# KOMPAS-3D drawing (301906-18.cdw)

Views: Вид А
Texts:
  Полумуфта
  Петров С.А.
  СПБГТИ(ТУ)
  Текст на чертеже
  Размерные надписи
  Шероховатость
  Линия-выноска #1
  Линия-выноска #2
  Линия-выноска #3
  Отклонения формы и база
  Заголовок таблицы
  Ячейка таблицы
  Стрелка вида
  Обозначение изменения
  Фигурная скобка
  Номер узла
  Марка координационной оси
  VRCB
  Выносная надпись
  Обозначение узла
  Марка/позиционное обозначение с линией-выноской
  Марка/позиционное обозначение на линии
  Марка/позиционное обозначение без линии-выноски
  Ra 2,5
  Rz 15
  1. Неуказанные предельные отклонения размеров валов h14,
  отверстий H14, остальных   IT 14/2
  Основной вид
  Rz 30
  Баранов Д.А.
  группа 364
  Сталь 12Х18Н10Т  Круг
Dimensions and other numbers on the sheet: 105.16.05.00.000; 7; 180; 220; 105; 120; 37; 25; 34,18; 65; 8; 2,5; 2; 70; 140; 5; 150; 0,5; 1:2,5; 14; 1; 105.16.05.00.000-; 0; 3; 4; 6; 9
